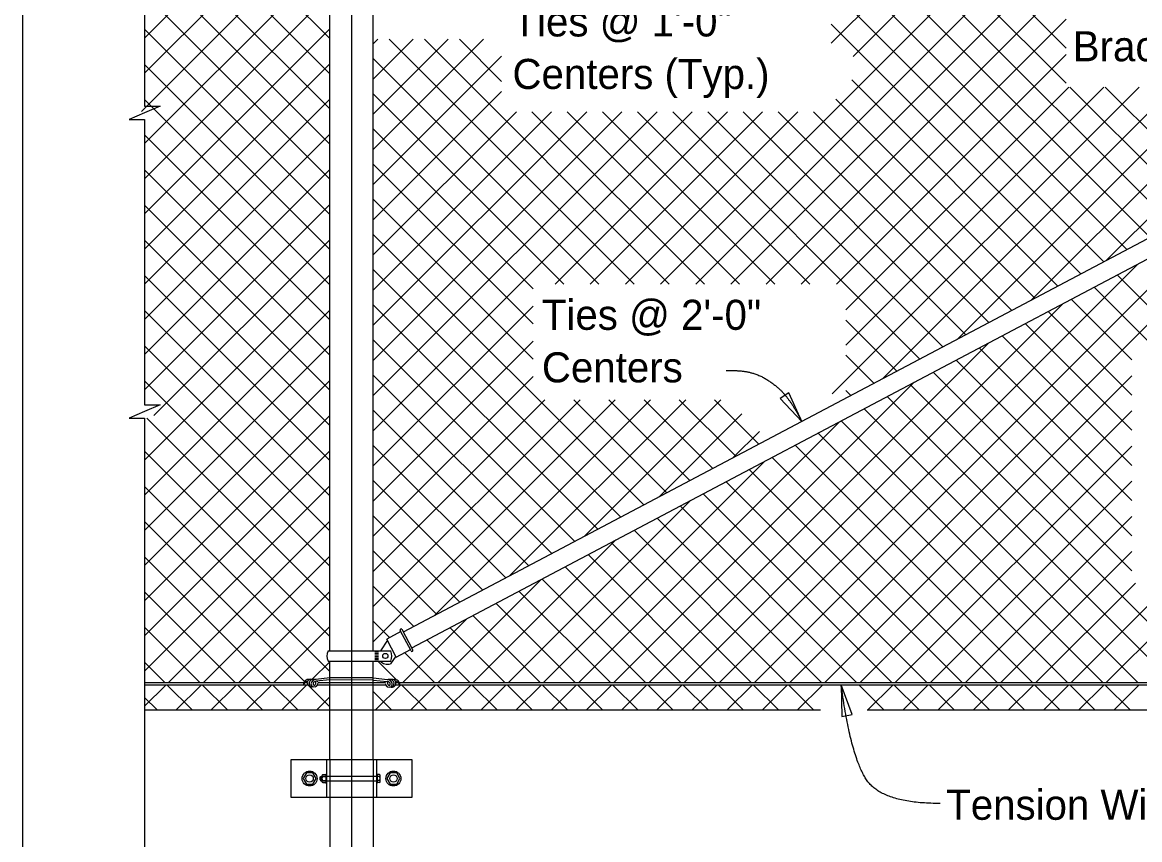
# Model space of a CAD drawing. Extents: x 0 to 72.1, y -7 to 30.
# Drawn here: x 0.02 to 7.5, y 18.32 to 23.8 of the extents above; entities that cross this region are included whole.
import ezdxf

# ---------------------------------------------------------------- set-up
doc = ezdxf.new("R2010")
doc.units = 0
for name, color, linetype in [('ActivePts-ConstElements', 7, 'Continuous'), ('AdhocPoint_dp', 7, 'Continuous'), ('Border', 7, 'Continuous'), ('Patterning', 7, 'Continuous'), ('PlotBorder_dp', 7, 'Continuous'), ('SheetBorder_dp', 7, 'Continuous'), ('TextMisc', 7, 'Continuous'), ('TextStructures', 7, 'Continuous')]:
    doc.layers.add(name, color=color, linetype=linetype)

msp = doc.modelspace()

# ---------------------------------------------------------------- linework, layer by layer
at = {"layer": 'ActivePts-ConstElements'}
msp.add_lwpolyline([(0.016, 2.0538), (41.2266, 2.0538), (41.2266, 28.0138), (0.016, 28.0138)], close=True, dxfattribs=at)
at = {"layer": 'AdhocPoint_dp'}
for p, q in [((7.2589, 25.0085), (4.2934, 22.043)), ((7.2652, 22.1934), (4.4502, 25.0085)), ((7.4946, 25.0085), (4.5291, 22.043)), ((7.4194, 22.2749), (4.6859, 25.0085)), ((7.7303, 25.0085), (4.7648, 22.043)), ((7.5736, 22.3564), (4.9216, 25.0085)), ((7.966, 25.0085), (5.0005, 22.043)), ((7.7279, 22.4379), (5.1573, 25.0085)), ((7.0117, 23.3898), (5.393, 25.0085)), ((6.7875, 25.0085), (5.4365, 23.6575)), ((7.0232, 25.0085), (5.5838, 23.5691)), ((7.0117, 23.6255), (5.6287, 25.0085)), ((2.0763, 24.9334), (0.8352, 23.6923)), ((2.0763, 23.6891), (0.8352, 24.9302)), ((2.0763, 24.6977), (0.8352, 23.4566)), ((2.0763, 23.4534), (0.8352, 24.6945)), ((2.0763, 24.462), (0.8142, 23.1998)), ((2.0763, 23.2177), (0.8352, 24.4588)), ((2.0763, 24.2263), (0.8352, 22.9852)), ((2.0763, 22.982), (0.8352, 24.2231)), ((2.0763, 23.9906), (0.8352, 22.7495)), ((2.0763, 22.7463), (0.8352, 23.9874)), ((7.0117, 23.8185), (5.2362, 22.043)), ((2.0763, 23.7549), (0.8352, 22.5138)), ((2.0763, 22.5106), (0.8352, 23.7517)), ((7.111, 22.112), (5.4365, 23.7865)), ((2.6347, 23.6842), (2.368, 23.4175)), ((2.399, 23.6842), (2.368, 23.6532)), ((2.8704, 23.6842), (2.368, 23.1818)), ((3.1061, 23.6842), (2.368, 22.946)), ((4.1158, 22.043), (2.4747, 23.6842)), ((4.3515, 22.043), (2.7104, 23.6842)), ((3.2282, 23.402), (2.9461, 23.6842)), ((2.0763, 23.5192), (0.8352, 22.2781)), ((2.0763, 22.2749), (0.8352, 23.516)), ((3.2282, 23.5705), (2.368, 22.7103)), ((3.8801, 22.043), (2.368, 23.5551)), ((7.0117, 23.5828), (5.4719, 22.043)), ((7.5003, 23.3643), (5.4435, 21.3075)), ((7.0289, 23.3643), (5.5348, 21.8702)), ((7.2646, 23.3643), (5.5348, 21.6345)), ((6.9568, 22.0305), (5.575, 23.4123)), ((7.736, 23.3643), (5.7806, 21.4089)), ((7.9717, 23.3643), (6.2804, 21.673)), ((8.2074, 23.3643), (6.7803, 21.9372)), ((7.8821, 22.5194), (7.0372, 23.3643)), ((8.0363, 22.6009), (7.2729, 23.3643)), ((8.4431, 23.3643), (7.2801, 22.2013)), ((3.2282, 23.3348), (2.368, 22.4746)), ((3.6444, 22.043), (2.368, 23.3194)), ((2.0763, 23.2835), (0.8352, 22.0424)), ((2.0763, 22.0392), (0.8352, 23.2803)), ((6.8026, 21.949), (5.4685, 23.283)), ((4.2704, 23.1985), (2.368, 21.2961)), ((3.799, 23.1985), (2.368, 21.7675)), ((3.3276, 23.1985), (2.368, 22.2389)), ((3.5633, 23.1985), (2.368, 22.0032)), ((4.0347, 23.1985), (2.368, 21.5318)), ((4.5061, 23.1985), (2.368, 21.0604)), ((4.5872, 22.043), (3.4317, 23.1985)), ((4.7418, 23.1985), (3.5863, 22.043)), ((4.8229, 22.043), (3.6674, 23.1985)), ((4.9775, 23.1985), (3.822, 22.043)), ((5.0586, 22.043), (3.9031, 23.1985)), ((5.2132, 23.1985), (4.0577, 22.043)), ((5.2943, 22.043), (4.1388, 23.1985)), ((6.0316, 21.5415), (4.3745, 23.1985)), ((6.1858, 21.623), (4.6102, 23.1985)), ((6.34, 21.7045), (4.8459, 23.1985)), ((6.4942, 21.786), (5.0816, 23.1985)), ((6.6484, 21.8675), (5.3173, 23.1985)), ((3.4393, 22.0124), (2.368, 23.0837)), ((2.0763, 23.0478), (0.8352, 21.8067)), ((2.0763, 21.8035), (0.8352, 23.0446)), ((3.4393, 21.7767), (2.368, 22.848)), ((2.0763, 22.8121), (0.8352, 21.571)), ((2.0763, 21.5678), (0.8352, 22.8089)), ((8.4921, 22.7062), (5.1573, 19.3714)), ((2.0763, 22.5764), (0.8352, 21.3353)), ((2.0763, 21.3321), (0.8352, 22.5732)), ((3.4393, 21.541), (2.368, 22.6123)), ((7.9922, 22.442), (4.9216, 19.3714)), ((2.0763, 21.0964), (0.8352, 22.3375)), ((2.0763, 22.3406), (0.8978, 21.1621)), ((4.181, 20.5636), (2.368, 22.3766)), ((7.4924, 22.1779), (4.6859, 19.3714)), ((2.0763, 22.1049), (0.8352, 20.8639)), ((2.0763, 20.8607), (0.8352, 22.1018)), ((4.0268, 20.4821), (2.368, 22.1409)), ((7.8815, 21.5771), (7.354, 22.1047)), ((7.6458, 21.5771), (7.1997, 22.0232)), ((7.4513, 21.5359), (7.0455, 21.9417)), ((2.0763, 21.8692), (0.8352, 20.6282)), ((2.0763, 20.625), (0.8352, 21.8661)), ((3.8726, 20.4006), (2.368, 21.9052)), ((3.4393, 21.8961), (2.368, 20.8247)), ((6.9926, 21.9137), (4.4502, 19.3714)), ((5.8773, 21.46), (5.5348, 21.8026)), ((7.4513, 21.3002), (6.8913, 21.8603)), ((7.4513, 21.0645), (6.7371, 21.7788)), ((3.7184, 20.3191), (2.368, 21.6695)), ((3.4393, 21.6604), (2.368, 20.589)), ((6.4927, 21.6496), (4.2145, 19.3714)), ((7.4513, 20.8288), (6.5829, 21.6973)), ((2.0763, 21.6335), (0.8352, 20.3925)), ((2.0763, 20.3893), (0.8352, 21.6304)), ((5.7231, 21.3785), (5.5348, 21.5669)), ((7.4513, 20.5931), (6.4287, 21.6158)), ((7.4513, 20.3574), (6.2745, 21.5343)), ((3.5642, 20.2376), (2.368, 21.4338)), ((3.4393, 21.4247), (2.368, 20.3533)), ((7.4513, 21.4297), (5.393, 19.3714)), ((7.4513, 20.1217), (6.1203, 21.4528)), ((2.0763, 21.3978), (0.8352, 20.1568)), ((2.0763, 20.1536), (0.8352, 21.3947)), ((5.9929, 21.3855), (3.9788, 19.3714)), ((7.966, 19.3714), (5.9661, 21.3713)), ((3.7545, 21.2684), (2.368, 19.8819)), ((3.5187, 21.2684), (2.368, 20.1176)), ((3.9902, 21.2684), (2.368, 19.6462)), ((4.2259, 21.2684), (2.7815, 19.824)), ((4.4616, 21.2684), (3.2813, 20.0881)), ((4.3353, 20.6451), (3.712, 21.2684)), ((4.6973, 21.2684), (3.7812, 20.3523)), ((4.4895, 20.7266), (3.9477, 21.2684)), ((4.6437, 20.8081), (4.1834, 21.2684)), ((4.7979, 20.8896), (4.4191, 21.2684)), ((4.9521, 20.9711), (4.6548, 21.2684)), ((5.5689, 21.297), (5.5348, 21.3312)), ((7.7303, 19.3714), (5.8118, 21.2898)), ((3.41, 20.1561), (2.368, 21.1981)), ((7.4513, 21.194), (5.6287, 19.3714)), ((7.4946, 19.3714), (5.6576, 21.2083)), ((2.0763, 21.1621), (0.8352, 19.921)), ((2.0763, 19.9179), (0.8499, 21.1443)), ((5.493, 21.1213), (3.7431, 19.3714)), ((4.8387, 21.1741), (4.281, 20.6164)), ((7.2589, 19.3714), (5.5034, 21.1268)), ((4.9565, 21.0562), (4.7809, 20.8806)), ((7.0232, 19.3714), (5.3492, 21.0453)), ((2.0763, 20.9264), (0.8352, 19.6853)), ((2.0763, 19.6822), (0.8352, 20.9233)), ((3.2558, 20.0746), (2.368, 20.9624)), ((6.7875, 19.3714), (5.195, 20.9638)), ((7.4513, 20.9583), (5.8644, 19.3714)), ((4.9932, 20.8572), (3.5073, 19.3714)), ((6.5518, 19.3714), (5.0408, 20.8824)), ((6.3161, 19.3714), (4.8866, 20.8009)), ((2.0763, 20.6907), (0.8352, 19.4496)), ((2.0763, 19.4465), (0.8352, 20.6876)), ((3.1016, 19.9931), (2.368, 20.7267)), ((6.0804, 19.3714), (4.7324, 20.7194)), ((7.4513, 20.7226), (6.1001, 19.3714)), ((4.4934, 20.5931), (3.2716, 19.3714)), ((5.8447, 19.3714), (4.5782, 20.6379)), ((5.609, 19.3714), (4.4239, 20.5564)), ((1.9069, 19.3802), (0.8352, 20.4519)), ((2.0763, 20.455), (0.9927, 19.3714)), ((2.9474, 19.9116), (2.368, 20.491)), ((5.3733, 19.3714), (4.2697, 20.4749)), ((7.4513, 20.4869), (6.3358, 19.3714)), ((5.1376, 19.3714), (4.1155, 20.3934)), ((3.9935, 20.3289), (3.0359, 19.3714)), ((4.9019, 19.3714), (3.9613, 20.3119)), ((2.0763, 20.2193), (1.2284, 19.3714)), ((2.7932, 19.8302), (2.368, 20.2553)), ((4.6662, 19.3714), (3.8071, 20.2304)), ((7.4513, 20.2512), (6.5715, 19.3714)), ((1.6801, 19.3714), (0.8352, 20.2162)), ((4.4305, 19.3714), (3.6529, 20.1489)), ((2.6389, 19.7487), (2.368, 20.0196)), ((3.4937, 20.0648), (2.8002, 19.3714)), ((4.1948, 19.3714), (3.4987, 20.0674)), ((7.4758, 20.04), (6.8072, 19.3714)), ((7.7115, 20.04), (7.0429, 19.3714)), ((7.9473, 20.04), (7.2786, 19.3714)), ((1.4444, 19.3714), (0.8352, 19.9805)), ((2.0763, 19.9836), (1.4641, 19.3714)), ((3.9591, 19.3714), (3.3445, 19.9859)), ((3.7234, 19.3714), (3.1903, 19.9045)), ((2.4772, 19.6747), (2.368, 19.7839)), ((2.9939, 19.8007), (2.5645, 19.3714)), ((3.4877, 19.3714), (3.036, 19.823)), ((1.2087, 19.3714), (0.8352, 19.7448)), ((2.0763, 19.7479), (1.6998, 19.3714)), ((3.252, 19.3714), (2.8818, 19.7415)), ((3.0163, 19.3714), (2.7276, 19.66)), ((2.7806, 19.3714), (2.5781, 19.5738)), ((0.973, 19.3714), (0.8352, 19.5091)), ((2.0763, 19.5122), (1.9589, 19.3948)), ((2.5289, 19.3873), (2.3993, 19.5169)), ((0.9779, 19.3566), (0.8352, 19.2139)), ((1.1544, 19.1899), (0.9877, 19.3566)), ((1.2136, 19.3566), (1.0469, 19.1899)), ((1.3901, 19.1899), (1.2234, 19.3566)), ((1.4493, 19.3566), (1.2826, 19.1899)), ((1.6258, 19.1899), (1.4591, 19.3566)), ((1.685, 19.3566), (1.5183, 19.1899)), ((1.8615, 19.1899), (1.6948, 19.3566)), ((1.9207, 19.3566), (1.754, 19.1899)), ((2.0763, 19.2108), (1.938, 19.3491)), ((2.5498, 19.3566), (2.3831, 19.1899)), ((2.5449, 19.3714), (2.5413, 19.3749)), ((2.7263, 19.1899), (2.5596, 19.3566)), ((2.7855, 19.3566), (2.6188, 19.1899)), ((2.962, 19.1899), (2.7953, 19.3566)), ((3.0212, 19.3566), (2.8545, 19.1899)), ((3.1977, 19.1899), (3.031, 19.3566)), ((3.2569, 19.3566), (3.0902, 19.1899)), ((3.4334, 19.1899), (3.2667, 19.3566)), ((3.4926, 19.3566), (3.3259, 19.1899)), ((3.6691, 19.1899), (3.5024, 19.3566)), ((3.7283, 19.3566), (3.5616, 19.1899)), ((3.9048, 19.1899), (3.7381, 19.3566)), ((3.964, 19.3566), (3.7973, 19.1899)), ((4.1405, 19.1899), (3.9738, 19.3566)), ((4.1997, 19.3566), (4.033, 19.1899)), ((4.3762, 19.1899), (4.2095, 19.3566)), ((4.4354, 19.3566), (4.2687, 19.1899)), ((4.6119, 19.1899), (4.4452, 19.3566)), ((4.6711, 19.3566), (4.5044, 19.1899)), ((4.8476, 19.1899), (4.6809, 19.3566)), ((4.9068, 19.3566), (4.7401, 19.1899)), ((5.0833, 19.1899), (4.9166, 19.3566)), ((5.1425, 19.3566), (4.9758, 19.1899)), ((5.319, 19.1899), (5.1523, 19.3566)), ((5.3782, 19.3566), (5.2116, 19.1899)), ((5.7904, 19.1899), (5.6237, 19.3566)), ((5.8496, 19.3566), (5.683, 19.1899)), ((6.0261, 19.1899), (5.8594, 19.3566)), ((6.0853, 19.3566), (5.9187, 19.1899)), ((6.2618, 19.1899), (6.0951, 19.3566)), ((6.321, 19.3566), (6.1544, 19.1899)), ((6.4975, 19.1899), (6.3308, 19.3566)), ((6.5567, 19.3566), (6.3901, 19.1899)), ((6.7332, 19.1899), (6.5665, 19.3566)), ((6.7924, 19.3566), (6.6258, 19.1899)), ((6.9689, 19.1899), (6.8022, 19.3566)), ((7.0281, 19.3566), (6.8615, 19.1899)), ((7.2046, 19.1899), (7.0379, 19.3566)), ((7.2638, 19.3566), (7.0972, 19.1899)), ((7.4403, 19.1899), (7.2736, 19.3566)), ((7.4995, 19.3566), (7.3329, 19.1899)), ((0.9187, 19.1899), (0.8352, 19.2734)), ((2.0731, 19.2733), (1.9897, 19.1899)), ((2.4906, 19.1899), (2.368, 19.3125)), ((2.0146, 18.7229), (2.0146, 18.735)), ((2.0203, 18.7229), (2.0203, 18.735))]:
    msp.add_line(p, q, dxfattribs=at)
at = {"layer": 'Border'}
for points in [[(0.8354, 25.192), (0.8354, 23.2357), (0.9387, 23.2357), (0.8354, 23.1907), (0.7321, 23.1457), (0.8354, 23.1457), (0.8354, 22.2521)], [(0.8354, 22.2521), (0.8354, 21.2344), (0.9387, 21.2344), (0.8354, 21.1894), (0.7321, 21.1444), (0.8354, 21.1444), (0.8354, 18.94)], [(0.8354, 19.19), (0.8354, 17.3392), (0.9387, 17.3392), (0.8354, 17.2942), (0.7321, 17.2492), (0.8354, 17.2492), (0.8354, 15.4114)]]:
    msp.add_lwpolyline(points, dxfattribs=at)
for points in [[(5.2397, 21.1231), (5.1527, 21.3156), (5.0942, 21.2762)], [(5.5038, 19.3567), (5.5088, 19.1455), (5.5781, 19.1589)]]:
    msp.add_lwpolyline(points, close=True, dxfattribs=at)
for points in [[(4.7336, 21.4635), (4.8873, 21.4709), (5.0778, 21.3636), (5.1909, 21.2206), (5.2397, 21.1231)], [(6.1668, 18.5627), (5.769, 18.5627), (5.565, 18.8996), (5.5038, 19.3566)]]:
    msp.add_open_spline(points, degree=2, dxfattribs=at)
at = {"layer": 'Patterning'}
for p, q in [((2.368, 19.3714), (2.0763, 19.3714)), ((2.368, 19.3566), (2.0763, 19.3566)), ((2.0763, 18.8548), (2.0763, 18.6048)), ((2.368, 18.8548), (2.368, 18.6048)), ((2.3889, 18.7444), (2.024, 18.7444)), ((2.024, 18.7145), (2.3889, 18.7145))]:
    msp.add_line(p, q, dxfattribs=at)
at = {"layer": 'PlotBorder_dp'}
for p, q in [((2.0763, 19.5847), (2.0763, 25.2299)), ((2.368, 19.5847), (2.368, 25.2299)), ((2.5696, 19.712), (11.8192, 24.6)), ((2.6255, 19.606), (11.8752, 24.494)), ((2.5529, 19.7147), (2.4586, 19.6649)), ((2.6212, 19.5855), (2.5488, 19.7227)), ((2.6331, 19.5918), (2.5606, 19.7289)), ((2.4628, 19.6569), (2.416, 19.5852)), ((2.5223, 19.5443), (2.4586, 19.6649)), ((2.065, 19.5847), (2.4848, 19.5847)), ((2.4024, 19.5784), (2.3789, 19.5784)), ((2.4024, 19.5686), (2.3789, 19.5686)), ((2.4024, 19.5569), (2.3789, 19.5569)), ((2.4024, 19.5451), (2.3789, 19.5451)), ((2.5189, 19.5509), (2.4841, 19.4978)), ((2.5223, 19.5443), (2.6166, 19.5942)), ((2.0651, 19.5169), (2.4848, 19.5169)), ((2.0763, 18.8548), (2.0763, 19.5169)), ((2.368, 18.8548), (2.368, 19.5169)), ((2.4024, 19.5343), (2.3789, 19.5343)), ((2.4024, 19.5247), (2.3789, 19.5247)), ((2.0768, 19.4057), (1.9825, 19.3945)), ((2.368, 19.404), (2.0768, 19.4057)), ((2.368, 19.404), (2.4629, 19.3929)), ((1.9019, 19.3714), (0.8353, 19.3714)), ((1.9314, 19.3566), (0.8353, 19.3566)), ((1.9256, 19.3714), (1.9103, 19.3714)), ((2.0768, 19.3911), (1.9847, 19.3817)), ((2.0763, 19.3566), (1.9933, 19.3566)), ((2.0763, 19.3714), (1.9959, 19.3714)), ((2.368, 19.3895), (2.0768, 19.3911)), ((2.368, 19.3895), (2.4606, 19.3799)), ((2.4502, 19.3714), (2.368, 19.3714)), ((2.4516, 19.3566), (2.368, 19.3566)), ((11.9143, 19.3566), (2.5165, 19.3566)), ((2.5332, 19.3714), (2.5201, 19.3714)), ((11.9129, 19.3714), (2.5432, 19.3714)), ((2.6282, 18.8548), (1.8162, 18.8548)), ((1.8162, 18.8548), (1.8162, 18.6048)), ((2.0555, 18.8548), (2.0555, 18.6048)), ((2.3888, 18.8548), (2.3888, 18.6048)), ((2.6282, 18.6048), (2.6282, 18.8548)), ((2.0118, 18.7378), (2.0174, 18.7444)), ((2.0118, 18.7201), (2.0118, 18.7378)), ((2.0174, 18.7444), (2.024, 18.7444)), ((2.0174, 18.7145), (2.0174, 18.7444)), ((2.024, 18.7477), (2.024, 18.712)), ((2.0287, 18.7428), (2.049, 18.7428)), ((2.0289, 18.7558), (2.049, 18.7558)), ((2.049, 18.7601), (2.049, 18.6995)), ((2.049, 18.7601), (2.0555, 18.7601)), ((2.049, 18.7558), (2.049, 18.7039)), ((2.3951, 18.7601), (2.3891, 18.7601)), ((2.3951, 18.7601), (2.3951, 18.6995)), ((2.4098, 18.7558), (2.3951, 18.7558)), ((2.41, 18.7428), (2.3951, 18.7428)), ((2.4149, 18.7104), (2.4149, 18.7493)), ((2.0118, 18.7201), (2.0174, 18.7145)), ((2.0174, 18.7145), (2.024, 18.7145)), ((2.0287, 18.7169), (2.049, 18.7169)), ((2.029, 18.7039), (2.049, 18.7039)), ((2.049, 18.6995), (2.0555, 18.6995)), ((2.3951, 18.6995), (2.3891, 18.6995)), ((2.41, 18.7168), (2.3951, 18.7168)), ((2.4098, 18.7038), (2.3951, 18.7038)), ((1.8162, 18.6048), (2.6282, 18.6048)), ((2.0763, 18.6048), (2.0763, 17.3548)), ((2.368, 18.6048), (2.368, 17.3548))]:
    msp.add_line(p, q, dxfattribs=at)
for points in [[(1.9629, 18.7674), (1.9195, 18.7674), (1.8978, 18.7298), (1.9195, 18.6923), (1.9629, 18.6923), (1.9845, 18.7298)], [(2.5248, 18.7674), (2.4815, 18.7674), (2.4598, 18.7298), (2.4815, 18.6923), (2.5248, 18.6923), (2.5465, 18.7298)]]:
    msp.add_lwpolyline(points, close=True, dxfattribs=at)
for centre, radius in [((1.9412, 18.7298), 0.05), ((1.9412, 18.7298), 0.025), ((2.5032, 18.7298), 0.05), ((2.5032, 18.7298), 0.025)]:
    msp.add_circle(centre, radius, dxfattribs=at)
for centre, radius, start, end in [((2.5545, 19.7259), 0.00673, 27.85098, 207.85098), ((2.627, 19.5887), 0.00673, 207.85098, 27.85098), ((2.0305, 18.7493), 0.00674, 104.48908, 254.18889), ((2.0434, 18.7298), 0.0196, 138.62797, 221.37203), ((2.4081, 18.7493), 0.00673, 285.7823, 75.54039), ((2.3952, 18.7298), 0.0196, 318.62797, 41.37203), ((2.0305, 18.7104), 0.00673, 105.7823, 255.54039), ((2.4081, 18.7104), 0.00674, 284.48908, 74.18889)]:
    msp.add_arc(centre, radius, start, end, dxfattribs=at)
for centre, major_axis, ratio, start_param, end_param in [((2.1341, 19.5509), (-0.0776, 0), 0.957868, 5.811591, 6.758603), ((2.4155, 19.551), (0.0776, 0), 0.957868, 5.810211, 6.75616), ((2.4675, 19.5661), (-0.0647, -0.0342), 0.957868, 0.271397, 1.331255), ((1.9369, 19.3589), (0.0373, 0), 0.957868, 1.486836, 3.108042), ((1.9494, 19.3733), (0.023, 0), 0.957868, 1.29026, 2.970541), ((1.9681, 19.368), (0.0295, 0), 0.957868, 1.220941, 4.039556), ((2.4777, 19.3662), (-0.0295, 0), 0.957868, 2.243629, 5.062245), ((2.4964, 19.3716), (-0.023, 0), 0.957868, 3.312645, 4.992926), ((1.958, 19.3192), (-0.0724, 0), 0.957868, 5.162149, 5.652106), ((1.9505, 19.3708), (-0.0249, 0), 0.957868, 6.009018, 7.089857), ((1.9519, 19.3668), (0.0231, 0), 0.957868, 3.779554, 4.879821), ((1.9816, 19.3697), (-0.0303, -0.0108), 0.724765, 4.35367, 6.324556), ((1.958, 19.3611), (0.0206, -0.0021), 0.798607, 4.32653, 5.220153), ((1.9715, 19.3611), (0.0206, -0.0021), 0.798607, 3.333154, 5.220153), ((1.9783, 19.3657), (-0.0139, 0), 0.957868, 5.22362, 6.905413), ((1.9726, 19.3633), (-0.00795, 0), 0.957868, 6.140374, 9.314262), ((1.9866, 19.3568), (-0.0259, 0), 0.957868, 4.777514, 5.62749), ((1.9709, 19.3691), (0.0119, 0), 0.957868, 5.725876, 7.416677), ((1.9641, 19.3799), (0.0391, 0), 0.957868, 5.082588, 5.41974), ((1.9709, 19.3691), (0.0119, 0), 0.957868, 5.639684, 5.723117), ((1.9711, 19.3678), (0.0251, 0), 0.957868, 5.531357, 6.227833), ((1.9711, 19.3678), (0.0251, 0), 0.957868, 0.407687, 0.609214), ((2.4746, 19.3661), (-0.0251, 0), 0.957868, 0.055352, 0.751829), ((2.4746, 19.3661), (-0.0251, 0), 0.957868, 5.673972, 5.875498), ((2.4817, 19.3781), (-0.0391, 0), 0.957868, 0.863445, 1.200597), ((2.4591, 19.3551), (0.0259, 0), 0.957868, 0.655696, 1.505671), ((2.4642, 19.368), (0.0303, -0.0108), 0.724765, 6.241815, 8.212701), ((2.4749, 19.3673), (-0.0119, 0), 0.957868, 5.149694, 6.840495), ((2.4749, 19.3673), (-0.0119, 0), 0.957868, 0.560069, 0.643501), ((2.4732, 19.3615), (0.00795, 0), 0.957868, 3.252108, 6.425997), ((2.4743, 19.3594), (-0.0206, -0.0021), 0.798607, 1.063032, 2.950031), ((2.4675, 19.3639), (0.0139, 0), 0.957868, 5.660958, 7.342751), ((2.4878, 19.3594), (-0.0206, -0.0021), 0.798607, 1.063032, 1.956656), ((2.4939, 19.365), (-0.0231, 0), 0.957868, 1.403365, 2.503632), ((2.5089, 19.3571), (-0.0373, 0), 0.957868, 3.175144, 4.79635), ((2.4953, 19.369), (0.0249, 0), 0.957868, 5.476514, 6.557353), ((2.4878, 19.3174), (0.0724, 0), 0.957868, 0.631079, 1.121037)]:
    msp.add_ellipse(centre, major_axis=major_axis, ratio=ratio, start_param=start_param, end_param=end_param, dxfattribs=at)
msp.add_ellipse((2.4488, 19.5514), major_axis=(-0.0178, 0), ratio=0.957868, dxfattribs=at)
at = {"layer": 'SheetBorder_dp'}
msp.add_line((2.2222, 27.5581), (2.2222, 16.7178), dxfattribs=at)
at = {"layer": 'TextMisc'}
for p, q in [((0.8353, 19.1899), (5.3655, 19.1899)), ((5.6787, 19.1899), (12.0764, 19.1899))]:
    msp.add_line(p, q, dxfattribs=at)

# ---------------------------------------------------------------- texts
at = {"layer": 'TextStructures'}
for s, p in [('Ties @ 1\'-0" ', (3.301, 23.7032)), ('Brace Rail', (7.0562, 23.5367)), ('Centers (Typ.)', (3.301, 23.3512)), ('Ties @ 2\'-0" ', (3.4981, 21.7369)), ('Centers', (3.4981, 21.3849)), ('Tension Wire', (6.2078, 18.4533))]:
    msp.add_text(s, height=0.2016, dxfattribs=at).set_placement(p)

doc.saveas('drawing.dxf')
